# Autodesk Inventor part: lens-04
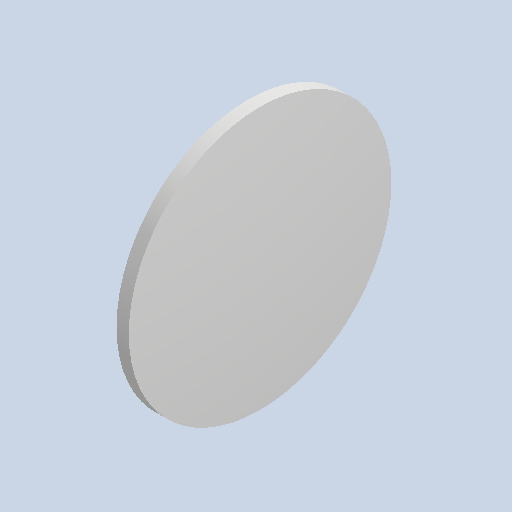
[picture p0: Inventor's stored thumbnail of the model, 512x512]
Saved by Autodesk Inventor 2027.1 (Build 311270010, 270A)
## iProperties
Created: 2026-07
Part Number: lens-04
Material: Generic
Document SubType Name: Modeling
Designer: dunge
Density: 1 g/cm^3
Appearance: Default
Author: dunge
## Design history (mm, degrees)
derived "lens.ipt"
feature "Lens::lens.ipt"
tag "TaggingFeature1"
node "Finishes"
node "Lens"
node "Finish1" dims "Finish1_Area" = 284.38957
other parameters: "SIDE_2_MINOR" = 0.635, "LENS_RADIUS" = 20.32, "SIDE_1_MINOR" = 1.27, "SIDE_1_MAJOR" = 2.54, "SIDE_2_MAJOR" = 1.27
